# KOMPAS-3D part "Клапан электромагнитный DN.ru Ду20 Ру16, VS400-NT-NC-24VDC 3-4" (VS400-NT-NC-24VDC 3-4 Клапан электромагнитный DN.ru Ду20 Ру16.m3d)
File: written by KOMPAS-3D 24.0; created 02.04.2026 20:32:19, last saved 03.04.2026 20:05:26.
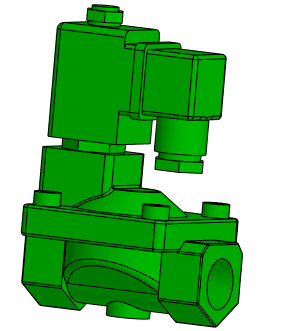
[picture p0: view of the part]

Document properties: Автор: artio; Полное имя файла: C:\Users\artio\OneDrive\Рабочий стол\Клапан электромагнитный DN.ru\VS400-NT-NC\VS400-NT-NC-24VDC 3-4 Клапан электромагнитный DN.ru Ду20 Ру16.m3d

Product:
- Body: Тело 1  | qty 1
    Масса: 1.210539
- Part/product: Клапан электромагнитный DN.ru Ду20 Ру16  | designation VS400-NT-NC-24VDC 3-4
    Масса: 0.954
    Раздел спецификации: Прочие изделия
    Примечание: D130-04727
    additional columns: ef56311e-7521-43dc-8291-0e6108b3d81d; VS400-ET-NC-220VAC 3-4; artio; c; Шероховатость не задана; Да

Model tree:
1. Операция без истории:1

Expressions: VS400-NT-NC-24VDC 3-4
